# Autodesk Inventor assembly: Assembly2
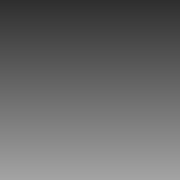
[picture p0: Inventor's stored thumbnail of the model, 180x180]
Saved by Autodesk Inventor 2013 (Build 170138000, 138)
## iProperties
Created: 2015-03
Part Number: Assembly2
Document SubType Name: Assembly
Designer: Uglješa
Author: Uglješa
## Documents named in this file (1)
- C:\Users\Uglješa\Desktop\Assembly2.iam
